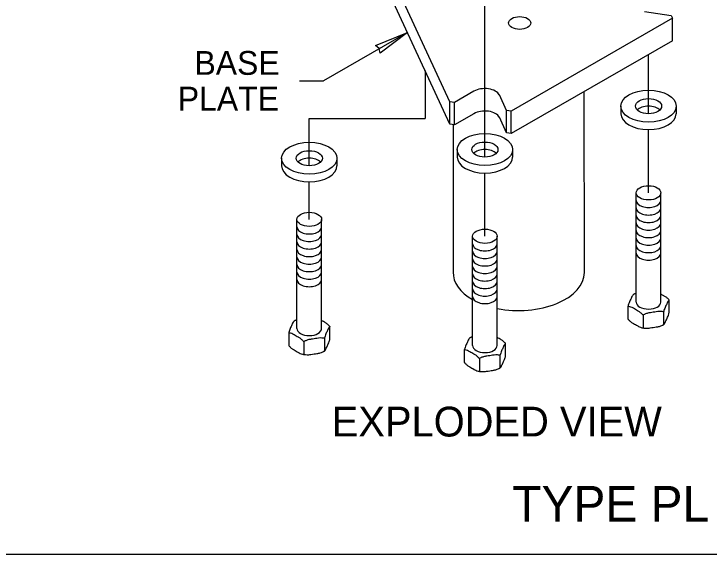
# Model space of a CAD drawing. Extents: x 99862 to 103151, y 100000 to 105076.
# Drawn here: x 101612.7 to 102079, y 99999.5 to 100362.2 of the extents above; entities that cross this region are included whole.
import ezdxf

# ---------------------------------------------------------------- set-up
doc = ezdxf.new("R2010")
doc.units = 0
for name, color, linetype in [('Level 1', 7, 'Continuous'), ('Level 12', 7, 'Continuous'), ('Level 15', 7, 'Continuous'), ('Level 16', 7, 'Continuous'), ('Level 20', 7, 'Continuous'), ('Level 5', 7, 'Continuous'), ('Level 6', 7, 'Continuous')]:
    doc.layers.add(name, color=color, linetype=linetype)

msp = doc.modelspace()

# ---------------------------------------------------------------- linework, layer by layer
at = {"layer": 'Level 1'}
msp.add_lwpolyline([(99862, 99999.5), (103151, 99999.5), (103151, 102075.5), (99862, 102075.5)], close=True, dxfattribs=at)
at = {"layer": 'Level 12'}
for p, q in [((102019.83, 100300.25), (102019.83, 100295.19)), ((102056.98, 100300.25), (102056.98, 100295.19)), ((101910.06, 100271.1), (101910.06, 100266.05)), ((101947.21, 100271.1), (101947.21, 100266.05)), ((101792.24, 100265.27), (101792.24, 100260.21)), ((101829.39, 100265.27), (101829.39, 100260.21)), ((102030.15, 100168.73), (102030.15, 100242.03)), ((102046.66, 100168.73), (102046.66, 100242.03)), ((101802.56, 100150.93), (101802.56, 100224.24)), ((101819.07, 100150.93), (101819.07, 100224.24)), ((101920.38, 100139.58), (101920.38, 100212.89)), ((101936.89, 100139.58), (101936.89, 100212.89)), ((102052.22, 100161.6), (102052.22, 100170.02)), ((102024.59, 100165.75), (102024.59, 100157.32)), ((102034.71, 100159.91), (102034.71, 100151.49)), ((102048.52, 100162.05), (102048.52, 100153.62)), ((101824.63, 100143.8), (101824.63, 100152.23)), ((101797.01, 100147.95), (101797.01, 100139.53)), ((101807.12, 100142.12), (101807.12, 100133.69)), ((101820.93, 100144.25), (101820.93, 100135.83)), ((101942.45, 100132.45), (101942.45, 100140.88)), ((101914.83, 100136.6), (101914.83, 100128.18)), ((101938.75, 100132.9), (101938.75, 100124.48)), ((101924.94, 100130.77), (101924.94, 100122.34))]:
    msp.add_line(p, q, dxfattribs=at)
for centre, major_axis in [((102038.41, 100300.25), (-18.57, 0)), ((102038.41, 100300.25), (-8.77, 0)), ((101928.64, 100271.1), (-18.57, 0)), ((101928.64, 100271.1), (-8.77, 0)), ((101810.82, 100265.27), (-18.57, 0)), ((101810.82, 100265.27), (-8.77, 0)), ((102038.41, 100242.03), (-8.26, 0)), ((101810.82, 100224.24), (-8.26, 0)), ((101928.64, 100212.89), (-8.26, 0))]:
    msp.add_ellipse(centre, major_axis=major_axis, ratio=0.57735, dxfattribs=at)
for centre, major_axis, start_param, end_param in [((102038.41, 100295.19), (-8.77, 0), 3.664192, 5.760586), ((102038.41, 100295.19), (18.57, 0), 3.141593, 6.283185), ((101928.64, 100266.05), (-8.77, 0), 3.664192, 5.760586), ((101810.82, 100260.21), (-8.77, 0), 3.664192, 5.760586), ((101928.64, 100266.05), (18.57, 0), 3.141593, 6.283185), ((101810.82, 100260.21), (18.57, 0), 3.141593, 6.283185), ((102038.41, 100236.98), (8.26, 0), 3.141588, 6.283185), ((102038.41, 100231.92), (8.26, 0), 3.141588, 6.283185), ((102038.41, 100226.87), (8.26, 0), 3.141588, 6.283185), ((102038.41, 100221.81), (8.26, 0), 3.141588, 6.283185), ((101810.82, 100219.18), (8.26, 0), 3.141588, 6.283185), ((102038.41, 100216.76), (8.26, 0), 3.141588, 6.283185), ((101810.82, 100214.13), (8.26, 0), 3.141588, 6.283185), ((102038.41, 100211.7), (8.26, 0), 3.141588, 6.283185), ((101810.82, 100209.07), (8.26, 0), 3.141588, 6.283185), ((101928.64, 100207.83), (8.26, 0), 3.141588, 6.283185), ((102038.41, 100206.65), (8.26, 0), 3.141588, 6.283185), ((101810.82, 100204.02), (8.26, 0), 3.141588, 6.283185), ((101928.64, 100202.78), (8.26, 0), 3.141588, 6.283185), ((102038.41, 100201.59), (8.26, 0), 3.141588, 6.283185), ((101810.82, 100198.96), (8.26, 0), 3.141588, 6.283185), ((101928.64, 100197.72), (8.26, 0), 3.141588, 6.283185), ((101810.82, 100193.91), (8.26, 0), 3.141588, 6.283185), ((101928.64, 100192.67), (8.26, 0), 3.141588, 6.283185), ((101810.82, 100188.85), (8.26, 0), 3.141588, 6.283185), ((101928.64, 100187.61), (8.26, 0), 3.141588, 6.283185), ((101810.82, 100183.8), (8.26, 0), 3.141588, 6.283185), ((101928.64, 100182.56), (8.26, 0), 3.141588, 6.283185), ((101928.64, 100177.5), (8.26, 0), 3.141588, 6.283185), ((101928.64, 100172.45), (8.26, 0), 3.141588, 6.283185), ((102038.41, 100168.73), (8.26, 0), 3.141593, 6.283185), ((101810.82, 100150.93), (8.26, 0), 3.141593, 6.283185), ((101928.64, 100139.58), (8.26, 0), 3.141593, 6.283185)]:
    msp.add_ellipse(centre, major_axis=major_axis, ratio=0.57735, start_param=start_param, end_param=end_param, dxfattribs=at)
for points, degree in [([(102028.19, 100173.68), (102028.14, 100173.65), (102028.08, 100173.6), (102027.56, 100173.04), (102026.95, 100171.66), (102026.45, 100170.57), (102025.94, 100169.48), (102025.33, 100168.25), (102024.77, 100166.42), (102024.68, 100166.09), (102024.59, 100165.75)], 3), ([(102028.81, 100174.04), (102028.62, 100173.94), (102028.44, 100173.83), (102028.24, 100173.71), (102028.21, 100173.7), (102028.19, 100173.68)], 3), ([(102030.15, 100174.61), (102029.85, 100174.5), (102029.55, 100174.39), (102029.12, 100174.2), (102028.96, 100174.12), (102028.81, 100174.04)], 3), ([(102052.22, 100170.02), (102052, 100170.31), (102051.74, 100170.6), (102050.2, 100172.1), (102048.54, 100172.98), (102047.16, 100173.78), (102047, 100173.87), (102046.83, 100173.97), (102046.66, 100174.07)], 3), ([(102052.22, 100170.02), (102052.14, 100170.01), (102052.04, 100169.94), (102051.48, 100169.34), (102050.87, 100167.96), (102050.37, 100166.87), (102049.86, 100165.78), (102049.26, 100164.55), (102048.69, 100162.72), (102048.6, 100162.39), (102048.52, 100162.05)], 3), ([(102034.71, 100159.91), (102034.49, 100160.2), (102034.23, 100160.49), (102032.69, 100161.99), (102031.03, 100162.87), (102029.65, 100163.67), (102028.27, 100164.47), (102026.61, 100165.49), (102025.07, 100165.77), (102024.81, 100165.79), (102024.59, 100165.75)], 3), ([(102048.52, 100162.05), (102048.22, 100162.17), (102047.86, 100162.24), (102045.76, 100162.53), (102043.5, 100162.11), (102041.61, 100161.82), (102039.72, 100161.53), (102037.46, 100161.25), (102035.36, 100160.31), (102035.01, 100160.12), (102034.71, 100159.91)], 3), ([(102048.62, 100153.66), (102048.68, 100153.69), (102048.73, 100153.74), (102049.26, 100154.3), (102049.86, 100155.68), (102050.37, 100156.77), (102050.87, 100157.86), (102051.48, 100159.1), (102052.04, 100160.92), (102052.14, 100161.26), (102052.22, 100161.6)], 3), ([(101800.6, 100155.89), (101800.55, 100155.86), (101800.5, 100155.81), (101799.97, 100155.25), (101799.36, 100153.87), (101798.86, 100152.78), (101798.35, 100151.69), (101797.75, 100150.46), (101797.18, 100148.63), (101797.09, 100148.29), (101797.01, 100147.95)], 3), ([(101801.22, 100156.24), (101801.03, 100156.14), (101800.85, 100156.04), (101800.65, 100155.92), (101800.63, 100155.9), (101800.6, 100155.89)], 3), ([(101802.56, 100156.81), (101802.26, 100156.71), (101801.96, 100156.6), (101801.53, 100156.4), (101801.38, 100156.33), (101801.22, 100156.24)], 3), ([(101824.63, 100152.23), (101824.41, 100152.52), (101824.15, 100152.8), (101822.61, 100154.3), (101820.96, 100155.19), (101819.58, 100155.98), (101819.41, 100156.08), (101819.24, 100156.18), (101819.07, 100156.28)], 3), ([(102024.59, 100157.32), (102024.81, 100157.03), (102025.07, 100156.75), (102026.61, 100155.25), (102028.27, 100154.36), (102029.65, 100153.57), (102031.01, 100152.78), (102032.64, 100151.77), (102033.93, 100151.52)], 3), ([(101824.63, 100152.23), (101824.55, 100152.22), (101824.46, 100152.15), (101823.89, 100151.55), (101823.29, 100150.17), (101822.78, 100149.08), (101822.27, 100147.99), (101821.67, 100146.76), (101821.11, 100144.93), (101821.01, 100144.59), (101820.93, 100144.25)], 3), ([(102033.93, 100151.52), (102034.57, 100151.39), (102035.21, 100151.3), (102035.85, 100151.23)], 2), ([(102035.84, 100151.23), (102037.6, 100151.03), (102039.78, 100151.43), (102041.61, 100151.72), (102043.5, 100152.01), (102045.76, 100152.29), (102047.69, 100153.15), (102047.85, 100153.23), (102048.01, 100153.31)], 3), ([(102048.01, 100153.31), (102048.19, 100153.41), (102048.37, 100153.51), (102048.57, 100153.63), (102048.6, 100153.65), (102048.62, 100153.66)], 3), ([(101807.12, 100142.12), (101806.9, 100142.41), (101806.64, 100142.69), (101805.1, 100144.19), (101803.44, 100145.08), (101802.06, 100145.87), (101800.68, 100146.67), (101799.03, 100147.7), (101797.49, 100147.98), (101797.23, 100147.99), (101797.01, 100147.95)], 3), ([(101820.93, 100144.25), (101820.63, 100144.37), (101820.28, 100144.45), (101818.17, 100144.74), (101815.91, 100144.32), (101814.02, 100144.02), (101812.14, 100143.73), (101809.87, 100143.45), (101807.77, 100142.52), (101807.42, 100142.33), (101807.12, 100142.12)], 3), ([(101821.04, 100135.87), (101821.09, 100135.9), (101821.14, 100135.95), (101821.67, 100136.51), (101822.27, 100137.89), (101822.78, 100138.98), (101823.29, 100140.07), (101823.89, 100141.3), (101824.46, 100143.13), (101824.55, 100143.46), (101824.63, 100143.8)], 3), ([(101918.42, 100144.54), (101918.37, 100144.51), (101918.32, 100144.46), (101917.79, 100143.9), (101917.18, 100142.52), (101916.68, 100141.43), (101916.17, 100140.34), (101915.57, 100139.11), (101915, 100137.28), (101914.91, 100136.94), (101914.83, 100136.6)], 3), ([(101919.04, 100144.89), (101918.85, 100144.79), (101918.67, 100144.69), (101918.47, 100144.57), (101918.45, 100144.55), (101918.42, 100144.54)], 3), ([(101920.38, 100145.46), (101920.08, 100145.36), (101919.78, 100145.25), (101919.35, 100145.05), (101919.2, 100144.98), (101919.04, 100144.89)], 3), ([(101942.45, 100140.88), (101942.23, 100141.17), (101941.97, 100141.45), (101940.43, 100142.95), (101938.78, 100143.84), (101937.4, 100144.63), (101937.23, 100144.73), (101937.06, 100144.83), (101936.89, 100144.92)], 3), ([(101942.45, 100140.88), (101942.37, 100140.87), (101942.28, 100140.8), (101941.71, 100140.2), (101941.11, 100138.82), (101940.6, 100137.73), (101940.09, 100136.64), (101939.49, 100135.4), (101938.93, 100133.58), (101938.83, 100133.24), (101938.75, 100132.9)], 3), ([(101797.01, 100139.53), (101797.23, 100139.24), (101797.49, 100138.95), (101799.03, 100137.45), (101800.68, 100136.57), (101802.06, 100135.77), (101803.42, 100134.99), (101805.05, 100133.98), (101806.35, 100133.72)], 3), ([(101924.94, 100130.77), (101924.72, 100131.06), (101924.46, 100131.34), (101922.92, 100132.84), (101921.26, 100133.73), (101919.88, 100134.52), (101918.5, 100135.32), (101916.85, 100136.35), (101915.31, 100136.63), (101915.05, 100136.64), (101914.83, 100136.6)], 3), ([(101806.35, 100133.72), (101806.98, 100133.6), (101807.63, 100133.5), (101808.26, 100133.43)], 2), ([(101808.26, 100133.43), (101810.01, 100133.23), (101812.2, 100133.64), (101814.02, 100133.92), (101815.91, 100134.21), (101818.17, 100134.49), (101820.11, 100135.35), (101820.26, 100135.43), (101820.42, 100135.52)], 3), ([(101820.42, 100135.51), (101820.61, 100135.62), (101820.79, 100135.72), (101820.98, 100135.84), (101821.01, 100135.85), (101821.04, 100135.87)], 3), ([(101938.75, 100132.9), (101938.45, 100133.02), (101938.1, 100133.1), (101935.99, 100133.39), (101933.73, 100132.96), (101931.84, 100132.67), (101929.96, 100132.38), (101927.7, 100132.1), (101925.59, 100131.17), (101925.24, 100130.98), (101924.94, 100130.77)], 3), ([(101938.86, 100124.52), (101938.91, 100124.55), (101938.96, 100124.6), (101939.49, 100125.16), (101940.09, 100126.54), (101940.6, 100127.63), (101941.11, 100128.72), (101941.71, 100129.95), (101942.28, 100131.78), (101942.37, 100132.11), (101942.45, 100132.45)], 3), ([(101914.83, 100128.18), (101915.05, 100127.89), (101915.31, 100127.6), (101916.85, 100126.1), (101918.5, 100125.22), (101919.88, 100124.42), (101921.24, 100123.64), (101922.87, 100122.63), (101924.17, 100122.37)], 3), ([(101924.17, 100122.37), (101924.8, 100122.25), (101925.45, 100122.15), (101926.08, 100122.08)], 2), ([(101926.08, 100122.08), (101927.83, 100121.88), (101930.02, 100122.29), (101931.84, 100122.57), (101933.73, 100122.86), (101935.99, 100123.14), (101937.93, 100124), (101938.08, 100124.08), (101938.24, 100124.17)], 3), ([(101938.24, 100124.16), (101938.43, 100124.27), (101938.61, 100124.37), (101938.8, 100124.49), (101938.83, 100124.5), (101938.86, 100124.52)], 3)]:
    msp.add_open_spline(points, degree=degree, dxfattribs=at)
at = {"layer": 'Level 15'}
for p in [(101876.6, 100349.76), (101804.3, 100317.26)]:
    msp.add_line(p, (101820.3, 100317.26), dxfattribs=at)
msp.add_lwpolyline([(101876.6, 100349.76), (101858.32, 100335.76), (101857.74, 100338.88), (101855.33, 100340.93)], close=True, dxfattribs=at)
at = {"layer": 'Level 16'}
for p, q in [((101928.64, 100266.04), (101928.64, 100384.18)), ((102038.41, 100295.19), (102038.41, 100334.98)), ((101888.47, 100324.17), (101888.47, 100292.03)), ((102038.41, 100242.03), (102038.41, 100284.47)), ((101928.64, 100212.89), (101928.64, 100255.33))]:
    msp.add_line(p, q, dxfattribs=at)
for points in [[(101810.82, 100260.2), (101810.82, 100292.03), (101888.47, 100292.03)], [(101810.82, 100224.24), (101810.82, 100249.49)]]:
    msp.add_lwpolyline(points, dxfattribs=at)
at = {"layer": 'Level 5'}
for p, q in [((101995.34, 100188.38), (101995.33, 100310.11)), ((101907.36, 100287.85), (101907.32, 100188.08))]:
    msp.add_line(p, q, dxfattribs=at)
for start_param, end_param in [(6.268969, 7.074155), (1.236588, 3.143698)]:
    msp.add_ellipse((101951.33, 100188.43), major_axis=(-44.01, 0), ratio=0.57735, start_param=start_param, end_param=end_param, dxfattribs=at)
at = {"layer": 'Level 6'}
for p, q in [((101905.17, 100303.24), (101865.63, 100388.45)), ((101905.17, 100288.18), (101865.63, 100373.39)), ((102035.81, 100363.82), (102053.52, 100361.08)), ((102053.52, 100361.08), (102054.37, 100359.26)), ((102054.37, 100359.26), (101946.33, 100296.88)), ((102054.37, 100344.2), (102054.37, 100359.26)), ((102054.37, 100344.2), (101946.33, 100281.82)), ((101921.29, 100310.24), (101908.33, 100302.76)), ((101943.17, 100297.37), (101938.32, 100307.82)), ((101905.17, 100288.18), (101905.17, 100303.24)), ((101908.33, 100302.76), (101905.17, 100303.24)), ((101908.33, 100287.7), (101908.33, 100302.76)), ((101921.29, 100295.18), (101908.33, 100287.7)), ((101946.33, 100296.88), (101943.17, 100297.37)), ((101943.17, 100282.31), (101943.17, 100297.37)), ((101946.33, 100281.82), (101946.33, 100296.88)), ((101943.17, 100282.31), (101938.32, 100292.76)), ((101908.33, 100287.7), (101905.17, 100288.18)), ((101946.33, 100281.82), (101943.17, 100282.31))]:
    msp.add_line(p, q, dxfattribs=at)
msp.add_ellipse((101951.95, 100356.09), major_axis=(-7.44, 0), ratio=0.57735, dxfattribs=at)
for centre in [(101928.6, 100306.2), (101928.6, 100291.14)]:
    msp.add_ellipse(centre, major_axis=(-10.11, 0), ratio=0.57735, start_param=3.423169, end_param=5.519376, dxfattribs=at)

# ---------------------------------------------------------------- texts
at = {"layer": 'Level 20'}
for s, height, p in [('BASE', 16, (101733.84, 100321.27)), ('PLATE', 16, (101722.67, 100297.27)), ('EXPLODED VIEW', 20, (101825.89, 100078.46)), ('TYPE PL SIGN SUPPORT', 24, (101947.04, 100021.25))]:
    msp.add_text(s, height=height, dxfattribs=at).set_placement(p)

doc.saveas('drawing.dxf')
